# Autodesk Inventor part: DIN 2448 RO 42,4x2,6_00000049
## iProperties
Created: 2006-03
Part Number: DIN 2448 RO 42,4x2,6_00000049
Material: Default
Document SubType Name: Modeling
Designer: Carlo
Stock Number: DIN 2448 RO 42,4x2,6
Mass: 507.137 g
Surface Area: 3914.3 cm^2
Volume: 507.137 cm^3
Density: 1 g/cm^3
G_L: 1590.000 mm
G_W: 42.400 mm
G_H: 42.400 mm
AFG_Item: 42.4 x 2.6
CSToolsMass: 1.0
CSToolsVolume: 507137.0
CSToolsArea: 3914.0
Author: Carlo
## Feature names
1. AFG_Detailed_DIN 2448 RO 42,4x2,6_00000049 [Extrusion]
2. AFG_Simplified_DIN 2448 RO 42,4x2,6_00000049 [Extrusion]
3. AFG_StartExtrusion_1 [Extrusion]
4. AFG_StartExtrusion_2 [Extrusion]
5. AFG_EndExtrusion_1 [Extrusion]
6. AFG_EndExtrusion_2 [Extrusion]
